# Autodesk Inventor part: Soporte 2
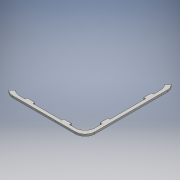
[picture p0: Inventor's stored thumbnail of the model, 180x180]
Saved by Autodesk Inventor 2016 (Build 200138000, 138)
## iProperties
Created: 2016-06
Part Number: Soporte 2
Material: Genérico
Document SubType Name: Modeling
Designer: adm
Density: 1 g/cm^3
Appearance: Valor por defecto
Author: adm
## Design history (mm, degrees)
sketch "Boceto1"
  geometry: L1 (10, 0)-(106, 0); L2 (121, 15)-(121, 126); L3 (116, 110)-(113, 110); L4 (113, 110)-(113, 98); L5 (113, 98)-(116, 98); L6 (116, 43)-(113, 43); L7 (113, 43)-(113, 31); L8 (113, 31)-(116, 31); L9 (36, 5)-(36, 8); L10 (36, 8)-(24, 8); L11 (24, 8)-(24, 5); L12 (92, 5)-(92, 8); L13 (92, 8)-(80, 8); L14 (80, 8)-(80, 5); L15 (101, 5)-(92, 5); L16 (80, 5)-(36, 5); L17 (24, 5)-(15, 5); L18 (116, 31)-(116, 20); L19 (116, 121)-(116, 110); L20 (116, 98)-(116, 43); L21 (121, 136)-(131, 136); L22 (-5, 5.005)-(-5, 5); L23 (-0.607, 4.393)-(4.393, 9.393); L24 (121, 136)-(121, 141); L25 (116.607, 136.607)-(111.607, 131.607); L26 (121, 141)-(131, 141); L27 (58, -7)-(58, -12.346); L28 (149, 70.5)-(183, 70.5); A1 r 15 centre (101, 20) between (101, 5) and (116, 20); A2 r 15 centre (106, 15) between (106, 0) and (121, 15); A3 r 15 centre (10, 15) between (-0.607, 4.393) and (10, 0); A4 r 15 centre (15, 20) between (4.393, 9.393) and (15, 5); A5 r 15 centre (101, 121) between (116, 121) and (111.607, 131.607); A6 r 15 centre (106, 126) between (121, 126) and (116.607, 136.607); 10 further points
  constraints: 56 end point, 12 perpendicular, 12 point on circle, 11 symmetric about line, 8 tangent, 6 centre point, 6 horizontal, 5 point on line, 4 parallel, 3 vertical, 4 other
  dimensions: "d5" = 15 radius of A1; "d6" = 15 radius of A2; "d7" = 12 distance of L3.end L4.end; "d11" = 12 distance of L6.end L7.end; "d12" = 55 distance between parallel lines of L6 L5; "d13" = 3 distance of L7.end L8.end; "d15" = 12 distance of L9.end L10.end; "d16" = 3 distance of L9.start L9.end; "d17" = 12 distance of L12.end L13.end; "d18" = 3 distance of L12.start L12.end; "d19" = 44 distance between parallel lines of L14 L9; "d26" = 116 distance from line of point (0, 0) L18; "d30" = 5 distance of L21.start L24.end; "d32" = 135 deg angle of L25 L26; "d34" = 70.5 distance between parallel lines of L1 L28
extrude "Extrusión1" new body sketch "Boceto1" distance "d20" = 3; taper "d21" = 0 deg
node "Sólido1"
other parameters: "d0" = 116, "d1" = 5, "d2" = 5
